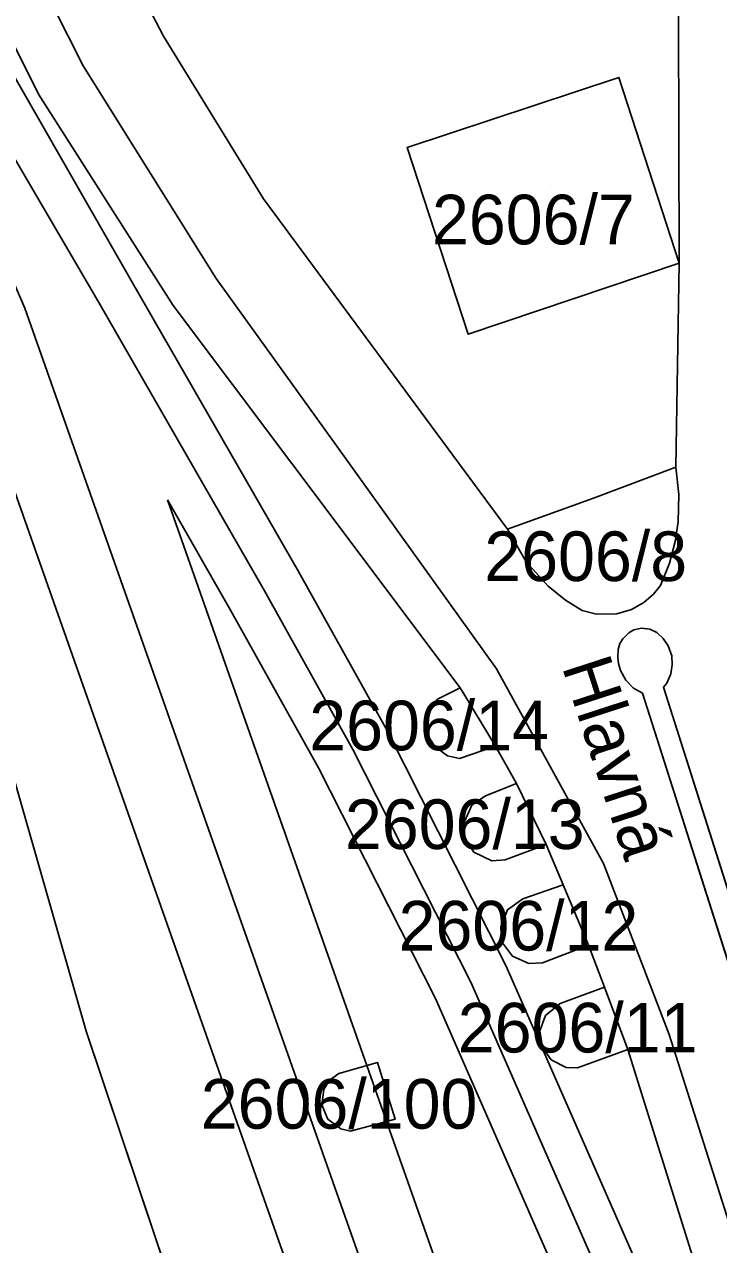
# Model space of a CAD drawing. Extents: x -263423 to -261326, y -1240067 to -1237864.
# Drawn here: x -262739.62 to -262711.63, y -1239816.07 to -1239766.9 of the extents above; entities that cross this region are included whole.
import ezdxf

# ---------------------------------------------------------------- set-up
doc = ezdxf.new("R2010")
doc.units = 0
for name, color, linetype in [('body_kn', 7, 'Continuous'), ('kladpar_druhypozemkov', 7, 'Continuous'), ('kladpar_hranice', 7, 'Continuous'), ('kladpar_parcelnecisla', 7, 'Continuous'), ('kladpar_plochy', 7, 'Continuous'), ('popisy', 7, 'Continuous'), ('tarchy_linie', 7, 'Continuous'), ('zappar_hrandruhpozemk', 7, 'Continuous')]:
    doc.layers.add(name, color=color, linetype=linetype)

msp = doc.modelspace()

# ---------------------------------------------------------------- linework, layer by layer
at = {"layer": 'body_kn'}
for p, q in [((-262734.02, -1239767.37), (-262734.02, -1239767.37)), ((-262737.25, -1239768.56), (-262737.25, -1239768.56)), ((-262715.65, -1239769.03), (-262715.65, -1239769.03)), ((-262739.05, -1239769.7), (-262739.05, -1239769.7)), ((-262724.19, -1239771.85), (-262724.19, -1239771.85)), ((-262724.19, -1239771.85), (-262724.19, -1239771.85)), ((-262729.99, -1239773.93), (-262729.99, -1239773.93)), ((-262713.22, -1239776.52), (-262713.22, -1239776.52)), ((-262735.26, -1239777.31), (-262735.26, -1239777.31)), ((-262731.89, -1239777.14), (-262731.89, -1239777.14)), ((-262739.61, -1239778.33), (-262739.61, -1239778.33)), ((-262736.62, -1239778.1), (-262736.62, -1239778.1)), ((-262733.62, -1239778.23), (-262733.62, -1239778.23)), ((-262721.73, -1239779.38), (-262721.73, -1239779.38)), ((-262727.09, -1239783.8), (-262727.09, -1239783.8)), ((-262728.84, -1239784.59), (-262728.84, -1239784.59)), ((-262713.36, -1239784.74), (-262713.36, -1239784.74)), ((-262713.36, -1239784.74), (-262713.36, -1239784.74)), ((-262733.86, -1239786.06), (-262733.86, -1239786.06)), ((-262733.86, -1239786.06), (-262733.86, -1239786.06)), ((-262716.68, -1239785.99), (-262716.68, -1239785.99)), ((-262713.23, -1239785.84), (-262713.23, -1239785.84)), ((-262713.26, -1239786.94), (-262713.26, -1239786.94)), ((-262720.14, -1239787.24), (-262720.14, -1239787.24)), ((-262720.14, -1239787.24), (-262720.14, -1239787.24)), ((-262713.38, -1239787.74), (-262713.38, -1239787.74)), ((-262719.39, -1239788.55), (-262719.39, -1239788.55)), ((-262713.61, -1239788.61), (-262713.61, -1239788.61)), ((-262728.57, -1239788.94), (-262728.57, -1239788.94)), ((-262718.51, -1239789.53), (-262718.51, -1239789.53)), ((-262713.97, -1239789.51), (-262713.97, -1239789.51)), ((-262729.94, -1239789.72), (-262729.94, -1239789.72)), ((-262717.8, -1239790.1), (-262717.8, -1239790.1)), ((-262714.26, -1239789.86), (-262714.26, -1239789.86)), ((-262731.31, -1239790.5), (-262731.31, -1239790.5)), ((-262717.14, -1239790.52), (-262717.14, -1239790.52)), ((-262715.14, -1239790.47), (-262715.14, -1239790.47)), ((-262714.65, -1239790.2), (-262714.65, -1239790.2)), ((-262716.55, -1239790.66), (-262716.55, -1239790.66)), ((-262715.74, -1239790.65), (-262715.74, -1239790.65)), ((-262715.25, -1239791.41), (-262715.25, -1239791.41)), ((-262715.05, -1239791.3), (-262715.05, -1239791.3)), ((-262714.74, -1239791.23), (-262714.74, -1239791.23)), ((-262714.4, -1239791.27), (-262714.4, -1239791.27)), ((-262714.13, -1239791.4), (-262714.13, -1239791.4)), ((-262715.68, -1239792.09), (-262715.68, -1239792.09)), ((-262715.62, -1239791.85), (-262715.62, -1239791.85)), ((-262715.5, -1239791.66), (-262715.5, -1239791.66)), ((-262713.87, -1239791.64), (-262713.87, -1239791.64)), ((-262713.66, -1239791.94), (-262713.66, -1239791.94)), ((-262715.7, -1239792.41), (-262715.7, -1239792.41)), ((-262713.52, -1239792.35), (-262713.52, -1239792.35)), ((-262720.59, -1239792.87), (-262720.59, -1239792.87)), ((-262715.67, -1239792.65), (-262715.67, -1239792.65)), ((-262715.59, -1239792.93), (-262715.59, -1239792.93)), ((-262713.56, -1239793.07), (-262713.56, -1239793.07)), ((-262713.5, -1239792.7), (-262713.5, -1239792.7)), ((-262715.37, -1239793.33), (-262715.37, -1239793.33)), ((-262713.72, -1239793.44), (-262713.72, -1239793.44)), ((-262722.06, -1239793.63), (-262722.06, -1239793.63)), ((-262715.06, -1239793.64), (-262715.06, -1239793.64)), ((-262714.7, -1239793.85), (-262714.7, -1239793.85)), ((-262713.85, -1239793.61), (-262713.85, -1239793.61)), ((-262723.29, -1239794.54), (-262723.29, -1239794.54)), ((-262722.97, -1239794.09), (-262722.97, -1239794.09)), ((-262722.97, -1239794.09), (-262722.97, -1239794.09)), ((-262724.99, -1239795.38), (-262724.99, -1239795.38)), ((-262723.42, -1239795.12), (-262723.42, -1239795.12)), ((-262723.31, -1239795.64), (-262723.31, -1239795.64)), ((-262723.08, -1239796), (-262723.08, -1239796)), ((-262720.63, -1239795.99), (-262720.63, -1239795.99)), ((-262726.38, -1239796.12), (-262726.38, -1239796.12)), ((-262722.57, -1239796.38), (-262722.57, -1239796.38)), ((-262722.08, -1239796.48), (-262722.08, -1239796.48)), ((-262727.77, -1239796.86), (-262727.77, -1239796.86)), ((-262719.78, -1239797.49), (-262719.78, -1239797.49)), ((-262719.78, -1239797.49), (-262719.78, -1239797.49)), ((-262721.03, -1239797.99), (-262721.03, -1239797.99)), ((-262721.03, -1239797.99), (-262721.03, -1239797.99)), ((-262721.58, -1239798.36), (-262721.58, -1239798.36)), ((-262721.92, -1239799.12), (-262721.92, -1239799.12)), ((-262721.85, -1239799.72), (-262721.85, -1239799.72)), ((-262718.59, -1239799.95), (-262718.59, -1239799.95)), ((-262721.5, -1239800.25), (-262721.5, -1239800.25)), ((-262720.77, -1239800.6), (-262720.77, -1239800.6)), ((-262720.24, -1239800.57), (-262720.24, -1239800.57)), ((-262716.28, -1239800.71), (-262716.28, -1239800.71)), ((-262717.9, -1239801.57), (-262717.9, -1239801.57)), ((-262717.9, -1239801.57), (-262717.9, -1239801.57)), ((-262719.52, -1239802.14), (-262719.52, -1239802.14)), ((-262719.52, -1239802.14), (-262719.52, -1239802.14)), ((-262720.14, -1239802.58), (-262720.14, -1239802.58)), ((-262720.42, -1239803.26), (-262720.42, -1239803.26)), ((-262720.39, -1239803.86), (-262720.39, -1239803.86)), ((-262716.88, -1239804), (-262716.88, -1239804)), ((-262720.21, -1239804.82), (-262720.21, -1239804.82)), ((-262719.95, -1239804.45), (-262719.95, -1239804.45)), ((-262719.28, -1239804.75), (-262719.28, -1239804.75)), ((-262718.73, -1239804.72), (-262718.73, -1239804.72)), ((-262721.63, -1239805.49), (-262721.63, -1239805.49)), ((-262716.23, -1239805.7), (-262716.23, -1239805.7)), ((-262716.23, -1239805.7), (-262716.23, -1239805.7)), ((-262723.05, -1239806.16), (-262723.05, -1239806.16)), ((-262718.02, -1239806.36), (-262718.02, -1239806.36)), ((-262718.02, -1239806.36), (-262718.02, -1239806.36)), ((-262718.61, -1239806.84), (-262718.61, -1239806.84)), ((-262737.14, -1239807.47), (-262737.14, -1239807.47)), ((-262718.84, -1239807.46), (-262718.84, -1239807.46)), ((-262713.63, -1239807.6), (-262713.63, -1239807.6)), ((-262718.74, -1239808.13), (-262718.74, -1239808.13)), ((-262715.29, -1239808.21), (-262715.29, -1239808.21)), ((-262715.29, -1239808.21), (-262715.29, -1239808.21)), ((-262725.39, -1239808.73), (-262725.39, -1239808.73)), ((-262718.39, -1239808.62), (-262718.39, -1239808.62)), ((-262726.94, -1239809.17), (-262726.94, -1239809.17)), ((-262726.94, -1239809.17), (-262726.94, -1239809.17)), ((-262717.78, -1239808.93), (-262717.78, -1239808.93)), ((-262717.32, -1239808.95), (-262717.32, -1239808.95)), ((-262727.33, -1239809.46), (-262727.33, -1239809.46)), ((-262727.55, -1239809.82), (-262727.55, -1239809.82)), ((-262727.63, -1239810.44), (-262727.63, -1239810.44)), ((-262727.39, -1239811.02), (-262727.39, -1239811.02)), ((-262724.68, -1239811.02), (-262724.68, -1239811.02)), ((-262726.87, -1239811.41), (-262726.87, -1239811.41)), ((-262726.48, -1239811.5), (-262726.48, -1239811.5))]:
    msp.add_line(p, q, dxfattribs=at)
at = {"layer": 'kladpar_druhypozemkov'}
for p, q in [((-262718.42, -1239773.37), (-262718.42, -1239773.37)), ((-262716.5, -1239787.74), (-262716.5, -1239787.74)), ((-262722.33, -1239795.09), (-262722.33, -1239795.09)), ((-262720.35, -1239799.04), (-262720.35, -1239799.04)), ((-262718.94, -1239803.28), (-262718.94, -1239803.28)), ((-262717.44, -1239807.32), (-262717.44, -1239807.32)), ((-262726.43, -1239810.57), (-262726.43, -1239810.57))]:
    msp.add_line(p, q, dxfattribs=at)
at = {"layer": 'kladpar_hranice'}
for points in [[(-262724.19, -1239771.85), (-262715.65, -1239769.03), (-262713.22, -1239776.52), (-262721.73, -1239779.38), (-262724.19, -1239771.85)], [(-262715.65, -1239769.03), (-262724.19, -1239771.85), (-262721.73, -1239779.38), (-262713.22, -1239776.52), (-262715.65, -1239769.03)], [(-262751.77, -1239786.69), (-262751.77, -1239786.37), (-262744.44, -1239783.54), (-262740.72, -1239794.96), (-262737.14, -1239807.47), (-262733.56, -1239818.12), (-262770.29, -1239828.28), (-262771.57, -1239828.53), (-262775.26, -1239828.89), (-262777.05, -1239829.08), (-262781.89, -1239829.56), (-262782.25, -1239824.59), (-262783.7, -1239805.41), (-262783.8, -1239804.54), (-262785.06, -1239793.68), (-262775.37, -1239792.25), (-262764.91, -1239790.65), (-262764.85, -1239790.96), (-262751.77, -1239786.69)], [(-262720.14, -1239787.24), (-262716.68, -1239785.99), (-262713.36, -1239784.74), (-262713.23, -1239785.84), (-262713.26, -1239786.94), (-262713.38, -1239787.74), (-262713.61, -1239788.61), (-262713.97, -1239789.51), (-262714.26, -1239789.86), (-262714.65, -1239790.2), (-262715.14, -1239790.47), (-262715.74, -1239790.65), (-262716.55, -1239790.66), (-262717.14, -1239790.52), (-262717.8, -1239790.1), (-262718.51, -1239789.53), (-262719.39, -1239788.55), (-262720.14, -1239787.24)], [(-262716.68, -1239785.99), (-262720.14, -1239787.24), (-262719.39, -1239788.55), (-262718.51, -1239789.53), (-262717.8, -1239790.1), (-262717.14, -1239790.52), (-262716.55, -1239790.66), (-262715.74, -1239790.65), (-262715.14, -1239790.47), (-262714.65, -1239790.2), (-262714.26, -1239789.86), (-262713.97, -1239789.51), (-262713.61, -1239788.61), (-262713.38, -1239787.74), (-262713.26, -1239786.94), (-262713.23, -1239785.84), (-262713.36, -1239784.74), (-262716.68, -1239785.99)], [(-262692.93, -1239862.21), (-262714.7, -1239793.85), (-262715.06, -1239793.64), (-262715.37, -1239793.33), (-262715.59, -1239792.93), (-262715.67, -1239792.65), (-262715.7, -1239792.41), (-262715.68, -1239792.09), (-262715.62, -1239791.85), (-262715.5, -1239791.66), (-262715.25, -1239791.41), (-262715.05, -1239791.3), (-262714.74, -1239791.23), (-262714.4, -1239791.27), (-262714.13, -1239791.4), (-262713.87, -1239791.64), (-262713.66, -1239791.94), (-262713.52, -1239792.35), (-262713.5, -1239792.7), (-262713.56, -1239793.07), (-262713.72, -1239793.44), (-262713.85, -1239793.61), (-262692.15, -1239862)], [(-262692.15, -1239862), (-262713.85, -1239793.61), (-262713.72, -1239793.44), (-262713.56, -1239793.07), (-262713.5, -1239792.7), (-262713.52, -1239792.35), (-262713.66, -1239791.94), (-262713.87, -1239791.64), (-262714.13, -1239791.4), (-262714.4, -1239791.27), (-262714.74, -1239791.23), (-262715.05, -1239791.3), (-262715.25, -1239791.41), (-262715.5, -1239791.66), (-262715.62, -1239791.85), (-262715.68, -1239792.09), (-262715.7, -1239792.41), (-262715.67, -1239792.65), (-262715.59, -1239792.93), (-262715.37, -1239793.33), (-262715.06, -1239793.64), (-262714.7, -1239793.85), (-262692.93, -1239862.21)], [(-262722.97, -1239794.09), (-262722.06, -1239793.63), (-262720.63, -1239795.99), (-262722.08, -1239796.48), (-262722.57, -1239796.38), (-262723.08, -1239796), (-262723.31, -1239795.64), (-262723.42, -1239795.12), (-262723.29, -1239794.54), (-262722.97, -1239794.09)], [(-262722.06, -1239793.63), (-262722.97, -1239794.09), (-262723.29, -1239794.54), (-262723.42, -1239795.12), (-262723.31, -1239795.64), (-262723.08, -1239796), (-262722.57, -1239796.38), (-262722.08, -1239796.48), (-262720.63, -1239795.99), (-262722.06, -1239793.63)], [(-262733.56, -1239818.12), (-262737.14, -1239807.47), (-262740.72, -1239794.96)], [(-262721.03, -1239797.99), (-262719.78, -1239797.49), (-262718.59, -1239799.95), (-262720.24, -1239800.57), (-262720.77, -1239800.6), (-262721.5, -1239800.25), (-262721.85, -1239799.72), (-262721.92, -1239799.12), (-262721.58, -1239798.36), (-262721.03, -1239797.99)], [(-262719.78, -1239797.49), (-262721.03, -1239797.99), (-262721.58, -1239798.36), (-262721.92, -1239799.12), (-262721.85, -1239799.72), (-262721.5, -1239800.25), (-262720.77, -1239800.6), (-262720.24, -1239800.57), (-262718.59, -1239799.95), (-262719.78, -1239797.49)], [(-262719.52, -1239802.14), (-262717.9, -1239801.57), (-262716.88, -1239804), (-262718.73, -1239804.72), (-262719.28, -1239804.75), (-262719.95, -1239804.45), (-262720.39, -1239803.86), (-262720.42, -1239803.26), (-262720.14, -1239802.58), (-262719.52, -1239802.14)], [(-262717.9, -1239801.57), (-262719.52, -1239802.14), (-262720.14, -1239802.58), (-262720.42, -1239803.26), (-262720.39, -1239803.86), (-262719.95, -1239804.45), (-262719.28, -1239804.75), (-262718.73, -1239804.72), (-262716.88, -1239804), (-262717.9, -1239801.57)], [(-262718.02, -1239806.36), (-262716.23, -1239805.7), (-262715.29, -1239808.21), (-262717.32, -1239808.95), (-262717.78, -1239808.93), (-262718.39, -1239808.62), (-262718.74, -1239808.13), (-262718.84, -1239807.46), (-262718.61, -1239806.84), (-262718.02, -1239806.36)], [(-262716.23, -1239805.7), (-262718.02, -1239806.36), (-262718.61, -1239806.84), (-262718.84, -1239807.46), (-262718.74, -1239808.13), (-262718.39, -1239808.62), (-262717.78, -1239808.93), (-262717.32, -1239808.95), (-262715.29, -1239808.21), (-262716.23, -1239805.7)], [(-262726.94, -1239809.17), (-262725.39, -1239808.73), (-262724.68, -1239811.02), (-262726.48, -1239811.5), (-262726.87, -1239811.41), (-262727.39, -1239811.02), (-262727.63, -1239810.44), (-262727.55, -1239809.82), (-262727.33, -1239809.46), (-262726.94, -1239809.17)], [(-262725.39, -1239808.73), (-262726.94, -1239809.17), (-262727.33, -1239809.46), (-262727.55, -1239809.82), (-262727.63, -1239810.44), (-262727.39, -1239811.02), (-262726.87, -1239811.41), (-262726.48, -1239811.5), (-262724.68, -1239811.02), (-262725.39, -1239808.73)]]:
    msp.add_lwpolyline(points, dxfattribs=at)
at = {"layer": 'kladpar_plochy'}
for p, q in [((-262715.65, -1239769.03), (-262724.19, -1239771.85)), ((-262713.22, -1239776.52), (-262715.65, -1239769.03)), ((-262724.19, -1239771.85), (-262721.73, -1239779.38)), ((-262721.73, -1239779.38), (-262713.22, -1239776.52)), ((-262713.36, -1239784.74), (-262716.68, -1239785.99)), ((-262713.23, -1239785.84), (-262713.36, -1239784.74)), ((-262716.68, -1239785.99), (-262720.14, -1239787.24)), ((-262713.26, -1239786.94), (-262713.23, -1239785.84)), ((-262713.38, -1239787.74), (-262713.26, -1239786.94)), ((-262720.14, -1239787.24), (-262719.39, -1239788.55)), ((-262713.61, -1239788.61), (-262713.38, -1239787.74)), ((-262719.39, -1239788.55), (-262718.51, -1239789.53)), ((-262713.97, -1239789.51), (-262713.61, -1239788.61)), ((-262718.51, -1239789.53), (-262717.8, -1239790.1)), ((-262714.26, -1239789.86), (-262713.97, -1239789.51)), ((-262717.8, -1239790.1), (-262717.14, -1239790.52)), ((-262714.65, -1239790.2), (-262714.26, -1239789.86)), ((-262717.14, -1239790.52), (-262716.55, -1239790.66)), ((-262715.74, -1239790.65), (-262715.14, -1239790.47)), ((-262715.14, -1239790.47), (-262714.65, -1239790.2)), ((-262716.55, -1239790.66), (-262715.74, -1239790.65)), ((-262715.25, -1239791.41), (-262715.5, -1239791.66)), ((-262715.05, -1239791.3), (-262715.25, -1239791.41)), ((-262714.74, -1239791.23), (-262715.05, -1239791.3)), ((-262714.4, -1239791.27), (-262714.74, -1239791.23)), ((-262714.13, -1239791.4), (-262714.4, -1239791.27)), ((-262713.87, -1239791.64), (-262714.13, -1239791.4)), ((-262715.68, -1239792.09), (-262715.7, -1239792.41)), ((-262715.62, -1239791.85), (-262715.68, -1239792.09)), ((-262715.5, -1239791.66), (-262715.62, -1239791.85)), ((-262713.66, -1239791.94), (-262713.87, -1239791.64)), ((-262713.52, -1239792.35), (-262713.66, -1239791.94)), ((-262715.7, -1239792.41), (-262715.67, -1239792.65)), ((-262713.5, -1239792.7), (-262713.52, -1239792.35)), ((-262715.67, -1239792.65), (-262715.59, -1239792.93)), ((-262715.59, -1239792.93), (-262715.37, -1239793.33)), ((-262713.72, -1239793.44), (-262713.56, -1239793.07)), ((-262713.56, -1239793.07), (-262713.5, -1239792.7)), ((-262715.37, -1239793.33), (-262715.06, -1239793.64)), ((-262713.85, -1239793.61), (-262713.72, -1239793.44)), ((-262722.06, -1239793.63), (-262722.97, -1239794.09)), ((-262720.63, -1239795.99), (-262722.06, -1239793.63)), ((-262715.06, -1239793.64), (-262714.7, -1239793.85)), ((-262714.7, -1239793.85), (-262692.93, -1239862.21)), ((-262692.15, -1239862), (-262713.85, -1239793.61)), ((-262723.29, -1239794.54), (-262723.42, -1239795.12)), ((-262722.97, -1239794.09), (-262723.29, -1239794.54)), ((-262737.14, -1239807.47), (-262740.72, -1239794.96)), ((-262723.42, -1239795.12), (-262723.31, -1239795.64)), ((-262723.31, -1239795.64), (-262723.08, -1239796)), ((-262723.08, -1239796), (-262722.57, -1239796.38)), ((-262722.08, -1239796.48), (-262720.63, -1239795.99)), ((-262722.57, -1239796.38), (-262722.08, -1239796.48)), ((-262719.78, -1239797.49), (-262721.03, -1239797.99)), ((-262718.59, -1239799.95), (-262719.78, -1239797.49)), ((-262721.03, -1239797.99), (-262721.58, -1239798.36)), ((-262721.58, -1239798.36), (-262721.92, -1239799.12)), ((-262721.92, -1239799.12), (-262721.85, -1239799.72)), ((-262721.85, -1239799.72), (-262721.5, -1239800.25)), ((-262720.24, -1239800.57), (-262718.59, -1239799.95)), ((-262721.5, -1239800.25), (-262720.77, -1239800.6)), ((-262720.77, -1239800.6), (-262720.24, -1239800.57)), ((-262717.9, -1239801.57), (-262719.52, -1239802.14)), ((-262716.88, -1239804), (-262717.9, -1239801.57)), ((-262719.52, -1239802.14), (-262720.14, -1239802.58)), ((-262720.14, -1239802.58), (-262720.42, -1239803.26)), ((-262720.42, -1239803.26), (-262720.39, -1239803.86)), ((-262720.39, -1239803.86), (-262719.95, -1239804.45)), ((-262718.73, -1239804.72), (-262716.88, -1239804)), ((-262719.95, -1239804.45), (-262719.28, -1239804.75)), ((-262719.28, -1239804.75), (-262718.73, -1239804.72)), ((-262716.23, -1239805.7), (-262718.02, -1239806.36)), ((-262715.29, -1239808.21), (-262716.23, -1239805.7)), ((-262718.02, -1239806.36), (-262718.61, -1239806.84)), ((-262718.61, -1239806.84), (-262718.84, -1239807.46)), ((-262733.56, -1239818.12), (-262737.14, -1239807.47)), ((-262718.84, -1239807.46), (-262718.74, -1239808.13)), ((-262718.74, -1239808.13), (-262718.39, -1239808.62)), ((-262717.32, -1239808.95), (-262715.29, -1239808.21)), ((-262725.39, -1239808.73), (-262726.94, -1239809.17)), ((-262724.68, -1239811.02), (-262725.39, -1239808.73)), ((-262718.39, -1239808.62), (-262717.78, -1239808.93)), ((-262726.94, -1239809.17), (-262727.33, -1239809.46)), ((-262717.78, -1239808.93), (-262717.32, -1239808.95)), ((-262727.33, -1239809.46), (-262727.55, -1239809.82)), ((-262727.55, -1239809.82), (-262727.63, -1239810.44)), ((-262727.63, -1239810.44), (-262727.39, -1239811.02)), ((-262727.39, -1239811.02), (-262726.87, -1239811.41)), ((-262726.48, -1239811.5), (-262724.68, -1239811.02)), ((-262726.87, -1239811.41), (-262726.48, -1239811.5))]:
    msp.add_line(p, q, dxfattribs=at)
for points in [[(-262724.19, -1239771.85), (-262715.65, -1239769.03), (-262713.22, -1239776.52), (-262721.73, -1239779.38)], [(-262751.77, -1239786.69), (-262751.77, -1239786.37), (-262744.44, -1239783.54), (-262740.72, -1239794.96), (-262737.14, -1239807.47), (-262733.56, -1239818.12), (-262770.29, -1239828.28), (-262771.57, -1239828.53), (-262775.26, -1239828.89), (-262777.05, -1239829.08), (-262781.89, -1239829.56), (-262782.25, -1239824.59), (-262783.7, -1239805.41), (-262783.8, -1239804.54), (-262785.06, -1239793.68), (-262775.37, -1239792.25), (-262764.91, -1239790.65), (-262764.85, -1239790.96)], [(-262720.14, -1239787.24), (-262716.68, -1239785.99), (-262713.36, -1239784.74), (-262713.23, -1239785.84), (-262713.26, -1239786.94), (-262713.38, -1239787.74), (-262713.61, -1239788.61), (-262713.97, -1239789.51), (-262714.26, -1239789.86), (-262714.65, -1239790.2), (-262715.14, -1239790.47), (-262715.74, -1239790.65), (-262716.55, -1239790.66), (-262717.14, -1239790.52), (-262717.8, -1239790.1), (-262718.51, -1239789.53), (-262719.39, -1239788.55)], [(-262722.97, -1239794.09), (-262722.06, -1239793.63), (-262720.63, -1239795.99), (-262722.08, -1239796.48), (-262722.57, -1239796.38), (-262723.08, -1239796), (-262723.31, -1239795.64), (-262723.42, -1239795.12), (-262723.29, -1239794.54)], [(-262721.03, -1239797.99), (-262719.78, -1239797.49), (-262718.59, -1239799.95), (-262720.24, -1239800.57), (-262720.77, -1239800.6), (-262721.5, -1239800.25), (-262721.85, -1239799.72), (-262721.92, -1239799.12), (-262721.58, -1239798.36)], [(-262719.52, -1239802.14), (-262717.9, -1239801.57), (-262716.88, -1239804), (-262718.73, -1239804.72), (-262719.28, -1239804.75), (-262719.95, -1239804.45), (-262720.39, -1239803.86), (-262720.42, -1239803.26), (-262720.14, -1239802.58)], [(-262718.02, -1239806.36), (-262716.23, -1239805.7), (-262715.29, -1239808.21), (-262717.32, -1239808.95), (-262717.78, -1239808.93), (-262718.39, -1239808.62), (-262718.74, -1239808.13), (-262718.84, -1239807.46), (-262718.61, -1239806.84)], [(-262726.94, -1239809.17), (-262725.39, -1239808.73), (-262724.68, -1239811.02), (-262726.48, -1239811.5), (-262726.87, -1239811.41), (-262727.39, -1239811.02), (-262727.63, -1239810.44), (-262727.55, -1239809.82), (-262727.33, -1239809.46)]]:
    msp.add_lwpolyline(points, close=True, dxfattribs=at)
msp.add_lwpolyline([(-262692.93, -1239862.21), (-262714.7, -1239793.85), (-262715.06, -1239793.64), (-262715.37, -1239793.33), (-262715.59, -1239792.93), (-262715.67, -1239792.65), (-262715.7, -1239792.41), (-262715.68, -1239792.09), (-262715.62, -1239791.85), (-262715.5, -1239791.66), (-262715.25, -1239791.41), (-262715.05, -1239791.3), (-262714.74, -1239791.23), (-262714.4, -1239791.27), (-262714.13, -1239791.4), (-262713.87, -1239791.64), (-262713.66, -1239791.94), (-262713.52, -1239792.35), (-262713.5, -1239792.7), (-262713.56, -1239793.07), (-262713.72, -1239793.44), (-262713.85, -1239793.61), (-262692.15, -1239862)], dxfattribs=at)
at = {"layer": 'tarchy_linie'}
for points in [[(-262657.08, -1239929.21), (-262646.38, -1239963), (-262674.82, -1239975.1), (-262703.83, -1239879.78), (-262739.61, -1239778.33), (-262778.19, -1239688.87), (-262817.29, -1239598.81)], [(-262714.55, -1239817.7), (-262720.21, -1239804.82), (-262724.99, -1239795.38), (-262728.57, -1239788.94), (-262735.26, -1239777.31), (-262742.03, -1239765.52)], [(-262716.01, -1239818.29), (-262721.63, -1239805.49), (-262726.38, -1239796.12), (-262729.94, -1239789.72), (-262736.62, -1239778.1), (-262741.1, -1239770.47)], [(-262706.54, -1239880.67), (-262742.27, -1239779.37)], [(-262733.86, -1239786.06), (-262731.31, -1239790.5), (-262727.77, -1239796.86), (-262723.05, -1239806.16), (-262717.47, -1239818.88), (-262715.31, -1239824.82), (-262709.31, -1239838.88), (-262708.04, -1239840.99), (-262702.91, -1239857), (-262700.03, -1239870.07), (-262696.82, -1239883.99), (-262694.57, -1239893.97), (-262689.49, -1239914.36), (-262686.73, -1239925.28), (-262678.36, -1239950.89), (-262673.78, -1239965.52), (-262673.54, -1239968), (-262672.3, -1239970.93), (-262673.02, -1239971.24), (-262701.12, -1239878.89), (-262733.86, -1239786.06)]]:
    msp.add_lwpolyline(points, dxfattribs=at)
at = {"layer": 'zappar_hrandruhpozemk'}
for p, q in [((-262734.02, -1239767.37), (-262739.09, -1239757.43)), ((-262739.05, -1239769.7), (-262733.62, -1239778.23)), ((-262731.89, -1239777.14), (-262727.09, -1239783.8)), ((-262719.78, -1239797.49), (-262720.63, -1239795.99)), ((-262717.9, -1239801.57), (-262718.59, -1239799.95)), ((-262716.23, -1239805.7), (-262716.88, -1239804)), ((-262713.63, -1239807.6), (-262693.57, -1239870.45))]:
    msp.add_line(p, q, dxfattribs=at)
for points in [[(-262752.45, -1239735.52), (-262742.22, -1239758.77), (-262737.25, -1239768.56), (-262731.89, -1239777.14)], [(-262754.38, -1239736.37), (-262744.15, -1239759.51), (-262739.05, -1239769.7)], [(-262713.36, -1239784.74), (-262713.22, -1239776.52), (-262713.25, -1239766.57), (-262713.59, -1239759.83)], [(-262720.14, -1239787.24), (-262729.99, -1239773.93), (-262734.02, -1239767.37)], [(-262733.62, -1239778.23), (-262728.84, -1239784.59), (-262722.06, -1239793.63)], [(-262727.09, -1239783.8), (-262720.59, -1239792.87), (-262716.28, -1239800.71), (-262713.63, -1239807.6)], [(-262715.29, -1239808.21), (-262695.55, -1239871.29), (-262693.57, -1239870.45)]]:
    msp.add_lwpolyline(points, dxfattribs=at)

# ---------------------------------------------------------------- texts
at = {"layer": 'kladpar_parcelnecisla'}
for s, p in [('2606/7', (-262723.191, -1239775.76)), ('2606/8', (-262721.082, -1239789.33)), ('2606/14', (-262728.14, -1239796.15)), ('2606/13', (-262726.702, -1239800.13)), ('2606/12', (-262724.536, -1239804.22)), ('2606/11', (-262722.15, -1239808.33)), ('2606/100', (-262732.513, -1239811.4))]:
    msp.add_text(s, height=2, dxfattribs=at).set_placement(p)
at = {"layer": 'popisy'}
msp.add_text('Hlavná', height=2, rotation=288, dxfattribs=at).set_placement((-262717.966, -1239792.765))

doc.saveas('drawing.dxf')
